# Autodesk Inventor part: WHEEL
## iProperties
Title: WHEEL
Author: J. DESIGNER
Comments: ECO 20001 CHANGES THE AXLE DIAMETER
Revision Number: A
Shininess: 20.0
Angle Display Precision: 2
Document Length Units: 11272
Document Angle Units: 11286
Document Time Units: 11279
Document Mass Units: 11290
Document Length Units Precision: 3
Document Angle Units Precision: 2
Compacted: False
PropertySet Name: _Private Model Information
Created: 2001-10
Part Number: ex6-1
User Status: ECO20001
Description: WHEEL
Document SubType Name: Modeling
Designer: E. MOSS
Control State: 0
Master: False
Checked Out: False
PropertySet Name: Design Tracking Control
Density: 0.0
Volumn: 0.0
Area: 0.0
PropertySet Name: Model Information
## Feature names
1. Revolution1
2. Tire [Revolution]
3. Extrusion1
4. Circular Pattern1
